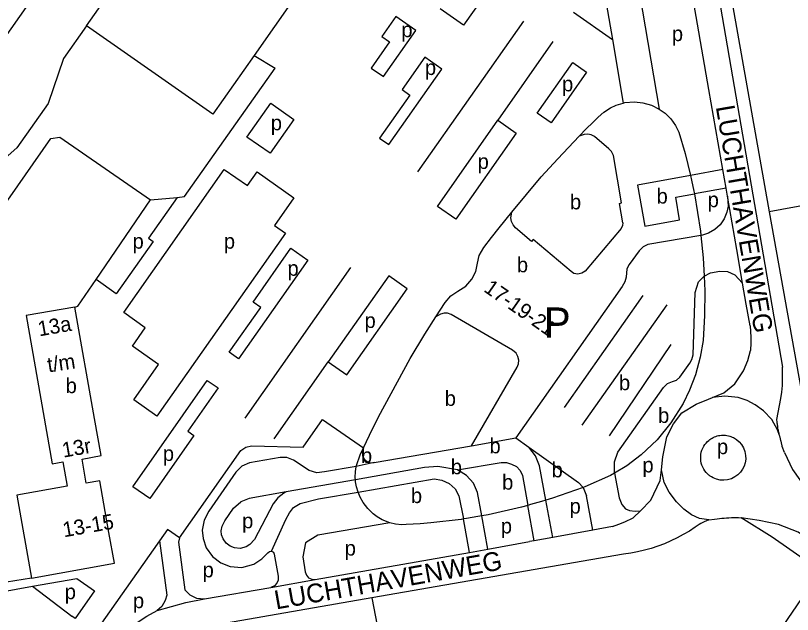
# Model space of a CAD drawing. Extents: x 154765 to 156627, y 383996 to 386132.
# Drawn here: x 155215.9 to 155422.2, y 385255.7 to 385414.8 of the extents above; entities that cross this region are included whole.
import ezdxf

# ---------------------------------------------------------------- set-up
doc = ezdxf.new("R2010")
doc.units = 0
for name, color, linetype in [('BLT_Basislijn', 7, 'Continuous'), ('BLT_Bebouwing', 7, 'Continuous'), ('BLT_Centroide', 7, 'Continuous'), ('BLT_Huisnummer_reeks', 7, 'Continuous'), ('BLT_Huisnummer_zonder_bebouwing', 7, 'Continuous'), ('BLT_Onderdoorgang_en_onderverdeling', 7, 'Continuous'), ('BLT_Straatnaam', 7, 'Continuous'), ('BLT_Tekst_parkeren', 7, 'Continuous'), ('BLT_Vlakafsluiter', 7, 'Continuous')]:
    doc.layers.add(name, color=color, linetype=linetype)

msp = doc.modelspace()

# ---------------------------------------------------------------- linework, layer by layer
at = {"layer": 'BLT_Basislijn'}
for p, q in [((155400.95, 385429.81), (155412.57, 385362.07)), ((155371.37, 385426.14), (155374.46, 385408.44)), ((155396.62, 385414.57), (155394.55, 385426.48)), ((155364.08, 385415.71), (155374.46, 385408.44)), ((155400, 385395.22), (155396.62, 385414.57)), ((155322.73, 385373.28), (155350.85, 385413.37)), ((155374.46, 385408.44), (155377.24, 385391.55)), ((155358.59, 385407.92), (155343.96, 385387.02)), ((155279.2, 385404.25), (155284.8, 385400.85)), ((155403.72, 385373.9), (155400, 385395.22)), ((155327.92, 385364.12), (155343.96, 385387.02)), ((155403.72, 385373.9), (155395.16, 385372.34)), ((155404.58, 385368.97), (155403.72, 385373.9)), ((155474.85, 385373.32), (155416.02, 385362.7)), ((155404.58, 385368.97), (155396.18, 385367.45)), ((155404.95, 385366.84), (155404.58, 385368.97)), ((155237.25, 385344.69), (155251.67, 385365.82)), ((155251.67, 385365.82), (155258.78, 385366.52)), ((155405.58, 385363.26), (155404.95, 385366.84)), ((155412.57, 385362.07), (155419.55, 385321.41)), ((155382.97, 385358.91), (155392.22, 385360.52)), ((155276.82, 385307.81), (155304.95, 385347.9)), ((155314.97, 385345.7), (155298.92, 385322.81)), ((155409.96, 385338.15), (155408.99, 385343.7)), ((155361.7, 385310.69), (155382.58, 385340.45)), ((155410.96, 385332.4), (155409.96, 385338.15)), ((155366.4, 385305.99), (155388.93, 385338)), ((155373.65, 385303.17), (155390.01, 385327.45)), ((155284.59, 385302.37), (155298.92, 385322.81)), ((155336.98, 385300.52), (155348.75, 385302.59)), ((155348.75, 385302.59), (155352.16, 385300.17)), ((155311.09, 385296.05), (155306.36, 385295.03)), ((155306.16, 385291.46), (155287.78, 385288.26)), ((155366.63, 385289.43), (155367.52, 385287.19)), ((155369.19, 385278.13), (155367.52, 385287.19)), ((155353.63, 385275.27), (155351.9, 385284.69)), ((155358.55, 385276.17), (155356.74, 385286.07)), ((155336.41, 385272.2), (155334.83, 385281.08)), ((155341.34, 385273.08), (155339.76, 385281.92)), ((155416.84, 385276.27), (155408.56, 385281.41)), ((155369.19, 385278.13), (155358.55, 385276.17)), ((155429.71, 385267.2), (155416.84, 385276.27)), ((155341.34, 385273.08), (155352.42, 385275.05)), ((155353.63, 385275.27), (155352.42, 385275.05)), ((155295.4, 385264.98), (155336.41, 385272.2)), ((155377.39, 385271.68), (155310.52, 385260.07)), ((155220.38, 385263.19), (155230.84, 385255.22)), ((155266.03, 385259.85), (155283.71, 385262.9)), ((155310.52, 385260.07), (155271.92, 385253.37))]:
    msp.add_line(p, q, dxfattribs=at)
for points in [[(155001.53, 385107.93), (155095.72, 385242.01), (155221.63, 385421.26), (155278.06, 385501.59), (155307.92, 385531.59), (155362.73, 385609.97), (155374.64, 385636.58)], [(155392.42, 385436.89), (155391.77, 385437.82), (155390.87, 385438.4), (155389.63, 385438.52), (155381.11, 385437.02), (155380.12, 385436.47), (155379.44, 385435.48), (155379.34, 385433.81), (155386.86, 385389.98)], [(155402.92, 385436.68), (155416.02, 385362.7)], [(155234.74, 385412.07), (155228.58, 385403.41), (155224.55, 385391.47), (155216.21, 385379.72), (155192.97, 385359.25), (155123.67, 385259.51), (155043.61, 385145.9), (155014.37, 385104.41), (155012.61, 385102.8), (155010.41, 385101.87), (155008.28, 385101.81), (155005.41, 385102.5), (155003.02, 385104.02), (155002.04, 385105.22), (155001.66, 385106.08), (155001.51, 385106.85), (155001.53, 385107.93)], [(155258.78, 385366.52), (155260.76, 385366.72), (155284.8, 385400.85)], [(155343.96, 385387.02), (155348.85, 385383.6), (155332.82, 385360.69), (155327.92, 385364.12)], [(155204.86, 385334.76), (155196.2, 385340.65), (155225.22, 385382.15), (155227.66, 385382.48), (155251.67, 385365.82)], [(155244.59, 385335.89), (155271.3, 385373.92), (155277.45, 385369.63), (155280.03, 385373.3), (155289.81, 385366.41), (155284.68, 385359.05), (155287.55, 385357.05), (155253.4, 385308.38), (155247.26, 385312.69), (155253.84, 385322.09), (155246.89, 385326.95), (155250.33, 385331.87), (155244.59, 385335.89)], [(155395.16, 385372.34), (155381.1, 385369.79), (155382.97, 385358.91)], [(155392.22, 385360.52), (155391.26, 385366.55), (155396.18, 385367.45)], [(155258.78, 385366.52), (155251.19, 385355.68), (155252.4, 385354.83), (155242.62, 385340.88), (155237.25, 385344.69)], [(155404.95, 385366.84), (155405.13, 385364.18), (155404.83, 385362.62), (155404.12, 385360.83), (155403.02, 385359.23), (155401.58, 385357.94), (155399.91, 385356.97), (155398.31, 385356.5), (155397.89, 385356.43)], [(155416.02, 385362.7), (155424.54, 385315.33), (155428.63, 385292.55)], [(155397.89, 385356.43), (155383.82, 385353.98), (155382.55, 385353.4), (155381.48, 385352.35), (155378.83, 385348.67), (155378.25, 385347.51), (155378.05, 385345.32), (155377.66, 385344.1), (155376.98, 385342.86), (155348.75, 385302.59)], [(155398.77, 385345.57), (155400.48, 385346.48), (155402.91, 385346.91), (155405, 385346.8), (155406.9, 385345.93), (155408.99, 385343.7)], [(155231.6, 385337.38), (155232.43, 385337.63), (155237.25, 385344.69)], [(155298.92, 385322.81), (155303.84, 385319.38), (155319.88, 385342.25), (155314.97, 385345.7)], [(155374.99, 385293.2), (155374.99, 385296.29), (155375.88, 385298.84), (155387.96, 385315.97), (155389.07, 385317.04), (155390.32, 385317.58), (155391.4, 385317.96), (155392.31, 385318.71), (155394.95, 385322.46), (155395.48, 385323.45), (155395.81, 385324.68), (155396.36, 385341.26), (155397.29, 385344.05), (155398.77, 385345.57)], [(155410.96, 385332.4), (155411.12, 385330.88), (155411.19, 385329.36), (155411.19, 385327.83), (155411.08, 385325.79)], [(155401, 385313.38), (155403.98, 385314.62), (155406.89, 385316.94), (155409.23, 385320.46), (155410.36, 385323.19), (155411.08, 385325.79)], [(155418.1, 385307.52), (155419.14, 385313.09), (155419.38, 385314.79), (155419.54, 385316.51), (155419.61, 385318.23), (155419.61, 385319.95), (155419.55, 385321.41)], [(155387.42, 385294.14), (155387.77, 385297.57), (155388.84, 385302.88), (155390.62, 385306.34), (155392.85, 385309.26), (155396.61, 385311.57), (155399.89, 385312.93), (155401, 385313.38)], [(155259.45, 385276.02), (155275.72, 385299.27), (155276.99, 385300.17), (155278.51, 385300.48), (155292.22, 385300.17), (155297.37, 385307.52), (155308.27, 385299.95)], [(155418.81, 385303.25), (155418.74, 385303.52), (155418.67, 385303.79), (155418.6, 385304.06), (155418.54, 385304.33), (155418.49, 385304.6), (155418.43, 385304.88), (155418.38, 385305.15), (155418.34, 385305.43), (155418.3, 385305.7), (155418.26, 385305.98), (155418.22, 385306.26), (155418.19, 385306.54), (155418.16, 385306.81), (155418.1, 385307.52)], [(155400, 385301.95), (155400.27, 385302.17), (155400.57, 385302.37), (155400.87, 385302.56), (155401.2, 385302.73), (155401.53, 385302.88), (155401.88, 385303.01), (155402.24, 385303.12), (155402.6, 385303.21), (155402.97, 385303.28), (155403.35, 385303.32), (155403.72, 385303.34), (155404.1, 385303.34), (155404.47, 385303.31), (155404.84, 385303.26), (155405.2, 385303.18), (155405.55, 385303.09), (155405.89, 385302.98), (155406.22, 385302.84), (155406.54, 385302.7)], [(155420.11, 385298.76), (155419.52, 385300.32), (155419.49, 385300.47), (155419.46, 385300.63), (155419.42, 385300.78), (155419.39, 385300.94), (155419.35, 385301.09), (155419.32, 385301.25), (155419.28, 385301.4), (155419.24, 385301.55), (155419.21, 385301.71), (155419.17, 385301.86), (155419.13, 385302.02), (155419.09, 385302.17), (155419.05, 385302.33), (155419.01, 385302.48), (155418.97, 385302.63), (155418.93, 385302.79), (155418.89, 385302.94), (155418.85, 385303.09), (155418.81, 385303.25)], [(155400, 385292.75), (155399.63, 385293.08), (155399.29, 385293.45), (155398.96, 385293.87), (155398.66, 385294.32), (155398.41, 385294.82), (155398.19, 385295.34), (155398.02, 385295.9), (155397.91, 385296.47), (155397.85, 385297.06), (155397.85, 385297.65), (155397.91, 385298.23), (155398.02, 385298.81), (155398.19, 385299.36), (155398.41, 385299.89), (155398.66, 385300.38), (155398.96, 385300.83), (155399.29, 385301.25), (155399.63, 385301.62), (155400, 385301.95)], [(155406.54, 385302.7), (155407.32, 385302.22), (155408.05, 385301.6), (155408.7, 385300.84), (155409.22, 385299.96), (155409.59, 385298.99), (155409.79, 385297.97), (155409.8, 385296.96), (155409.66, 385295.99), (155409.38, 385295.1), (155408.97, 385294.29), (155408.43, 385293.52), (155407.74, 385292.82), (155406.92, 385292.23), (155406, 385291.77), (155405, 385291.48), (155403.99, 385291.37), (155402.99, 385291.42), (155402.05, 385291.63), (155401.2, 385291.97)], [(155356.74, 385286.07), (155355.05, 385295.15), (155353.93, 385297.88), (155352.16, 385300.17)], [(155352.16, 385300.17), (155365.37, 385290.8), (155366.63, 385289.43)], [(155306.36, 385295.03), (155297.93, 385293.57), (155295.9, 385293.37), (155293.87, 385293.92), (155289.67, 385296.67), (155287.96, 385297.36), (155286.11, 385297.39), (155277.99, 385295.96), (155275.94, 385295.06), (155274.37, 385293.46), (155267.17, 385283.18), (155265.94, 385280.78), (155265.47, 385278.13), (155265.65, 385275.86), (155266.49, 385273.43), (155268.15, 385271.1), (155270.35, 385269.42), (155272.86, 385268.44), (155275.96, 385268.2), (155279.15, 385269.05), (155281.31, 385270.44), (155282.84, 385272.09), (155283.32, 385272.46), (155283.88, 385272.48)], [(155420.11, 385298.76), (155422.23, 385294.2), (155425.65, 385289.38), (155428.46, 385286.31), (155495.6, 385239.29)], [(155333.27, 385294.1), (155328.03, 385295.03), (155324.48, 385294.7), (155306.16, 385291.46)], [(155333.27, 385294.1), (155344.83, 385296.07), (155346.27, 385296.07), (155347.64, 385295.65), (155348.91, 385294.97), (155349.93, 385293.95), (155350.51, 385292.63), (155351.9, 385284.69)], [(155339.76, 385281.92), (155338.6, 385288.08), (155337.46, 385290.59), (155335.63, 385292.66), (155333.27, 385294.1)], [(155374.99, 385293.2), (155376.19, 385286.65), (155376.9, 385284.87), (155377.9, 385283.79), (155378.94, 385283.33), (155380.41, 385283.12), (155381.82, 385283.25)], [(155381.82, 385283.25), (155384.63, 385286.07), (155387.13, 385291.29), (155387.42, 385294.14)], [(155401.2, 385291.97), (155400.74, 385292.22), (155400.36, 385292.47), (155400.3, 385292.52), (155400.18, 385292.61), (155400, 385292.75)], [(155306.84, 385288.21), (155327.04, 385291.7), (155329.13, 385291.42), (155331.05, 385290.52), (155332.59, 385289.07), (155333.64, 385287.24), (155334.83, 385281.08)], [(155287.78, 385288.26), (155287.08, 385287.95), (155285.51, 385286.67), (155284.31, 385285.13), (155279.31, 385275.63), (155278.07, 385274.3), (155277.11, 385273.68), (155275.5, 385273.25), (155273.99, 385273.37), (155272.83, 385273.82), (155271.79, 385274.62), (155270.98, 385275.75), (155270.58, 385276.89), (155270.51, 385277.89), (155270.73, 385279.17), (155271.46, 385280.59), (155273.78, 385283.91), (155275.71, 385285.63)], [(155287.78, 385288.26), (155277.88, 385286.54), (155275.71, 385285.63)], [(155283.88, 385272.48), (155287.65, 385280.93), (155288.66, 385282.67), (155289.69, 385284.08), (155291.5, 385285.18), (155296.33, 385286.4), (155306.84, 385288.21)], [(155400, 385280.8), (155398.78, 385280.33), (155397.88, 385279.84), (155397.45, 385279.6), (155396.4, 385278.86)], [(155400, 385280.8), (155401.56, 385281.04), (155402.19, 385281.13), (155402.82, 385281.2), (155403.46, 385281.27), (155404.09, 385281.32), (155404.73, 385281.37), (155405.37, 385281.4), (155406.01, 385281.42), (155406.65, 385281.44), (155407.28, 385281.44), (155407.92, 385281.43), (155408.56, 385281.41)], [(155432.59, 385271.29), (155423.74, 385277.53), (155418.53, 385279.58), (155413.38, 385280.64), (155408.56, 385281.41)], [(155259.45, 385276.02), (155256.19, 385278.3), (155254.07, 385275.28)], [(155315.32, 385280.04), (155296.16, 385276.77), (155292.92, 385274.73), (155292.13, 385270.98), (155292.79, 385266.99), (155293.11, 385266.13), (155293.7, 385265.47), (155294.53, 385265.06), (155295.4, 385264.98)], [(155396.4, 385278.86), (155394.84, 385277.85), (155393.24, 385276.9), (155391.6, 385276.02), (155389.92, 385275.22), (155388.21, 385274.49), (155386.46, 385273.83), (155384.7, 385273.24), (155382.9, 385272.74), (155381.09, 385272.31), (155379.27, 385271.96), (155377.39, 385271.68)], [(155254.07, 385275.28), (155238.1, 385252.48), (155236.88, 385253.34), (155229.4, 385242.68)], [(155254.07, 385275.28), (155256.01, 385260.8), (155255.64, 385259.42), (155254.7, 385257.83), (155253.51, 385256.71)], [(155259.45, 385276.02), (155259.16, 385274.94), (155260.86, 385262.27), (155262.17, 385260.89), (155263.96, 385260.03), (155266.03, 385259.85)], [(155283.88, 385272.48), (155284.34, 385272.21), (155284.59, 385271.69), (155285.61, 385265.87), (155285.63, 385264.83), (155285.29, 385263.98), (155284.66, 385263.31), (155283.71, 385262.9)], [(155393.24, 385209.32), (155391.13, 385210.77), (155429.71, 385267.2)], [(155220.06, 385265.38), (155211.16, 385263.89), (155211.57, 385261.6), (155220.38, 385263.19)], [(155220.38, 385263.19), (155232.1, 385265.26), (155236.79, 385261.97), (155231.66, 385254.64), (155230.84, 385255.22)], [(155253.51, 385256.71), (155261.05, 385258.86), (155266.03, 385259.85)], [(155310.52, 385260.07), (155314.18, 385240.81)], [(155248.17, 385253.56), (155250.76, 385255.2), (155253.51, 385256.71)]]:
    msp.add_lwpolyline(points, dxfattribs=at)
for points in [[(155316.89, 385414.57), (155313.19, 385409.29), (155315.23, 385407.86), (155310.35, 385400.89), (155313.62, 385398.59), (155322.21, 385410.86)], [(155312.54, 385382.26), (155315, 385380.53), (155329.06, 385400.6), (155324.54, 385403.74), (155318.54, 385395.16), (155320.58, 385393.71)], [(155363.87, 385402.39), (155367.56, 385399.78), (155358.09, 385386.29), (155354.44, 385388.88)], [(155283.64, 385391.52), (155289.78, 385387.22), (155283.47, 385378.22), (155277.31, 385382.53)], [(155288.98, 385352.99), (155293.46, 385349.82), (155275.1, 385323.65), (155272.64, 385325.37), (155280.99, 385337.27), (155278.94, 385338.68)], [(155266.79, 385317.89), (155269.65, 385315.88), (155261.61, 385304.39), (155263.24, 385303.26), (155251.51, 385286.48), (155247.03, 385289.62)]]:
    msp.add_lwpolyline(points, close=True, dxfattribs=at)
at = {"layer": 'BLT_Bebouwing'}
for p, q in [((155234.74, 385412.07), (155261.63, 385451)), ((155301.33, 385435.8), (155279.2, 385404.25)), ((155268.23, 385388.61), (155234.74, 385412.07)), ((155279.2, 385404.25), (155268.23, 385388.61)), ((155375.38, 385391.03), (155377.24, 385391.55)), ((155220.06, 385265.38), (155242.15, 385269.29))]:
    msp.add_line(p, q, dxfattribs=at)
for points in [[(155348.18, 385419.98), (155342.9, 385423.71), (155334.85, 385412.23), (155328.66, 385416.58)], [(155377.24, 385391.55), (155377.74, 385391.69), (155380.29, 385391.9), (155382.48, 385391.68), (155384.81, 385391), (155386.86, 385389.98)], [(155365.58, 385382.75), (155367.52, 385384.79), (155369.09, 385386.34), (155370.64, 385387.85), (155372.13, 385389.14), (155373.85, 385390.31), (155375.38, 385391.03)], [(155386.86, 385389.98), (155388.38, 385388.88), (155389.91, 385387.38), (155391.18, 385385.61), (155392.07, 385383.84), (155393.72, 385378.14), (155395.16, 385372.34)], [(155347.72, 385362.57), (155355.51, 385371.95), (155359.88, 385376.78), (155365.58, 385382.75)], [(155395.16, 385372.34), (155395.43, 385371.11), (155396.04, 385368.18), (155396.18, 385367.45)], [(155396.18, 385367.45), (155397.76, 385357.51), (155397.89, 385356.43)], [(155327.54, 385334.8), (155329.95, 385338.57), (155331.49, 385340.4), (155333.36, 385341.57), (155335.44, 385342.9), (155337.09, 385344.75), (155338.13, 385346.83), (155338.59, 385349.02), (155339.05, 385351.06), (155340.26, 385353.21), (155342.26, 385355.84), (155344.28, 385358.44), (155347.72, 385362.57)], [(155397.89, 385356.43), (155398.48, 385350.42), (155398.77, 385345.57)], [(155398.77, 385345.57), (155398.92, 385341.66), (155398.89, 385335.14), (155398.52, 385328.45), (155397.75, 385324.02), (155396.47, 385319.4), (155394.88, 385315.26), (155393.16, 385311.72), (155389.93, 385306.57), (155386.29, 385302.13), (155382.04, 385298.1), (155378.19, 385295.19), (155374.99, 385293.2)], [(155231.6, 385337.38), (155218.64, 385335.1), (155225.56, 385295.74), (155228.43, 385296.24)], [(155236.82, 385307.8), (155231.6, 385337.38)], [(155308.27, 385299.95), (155309.88, 385303.32), (155312.3, 385308.23), (155320.69, 385323.67), (155324.58, 385330.17), (155327.54, 385334.8)], [(155233.52, 385297), (155238.56, 385297.89), (155236.82, 385307.8)], [(155306.36, 385295.03), (155307.52, 385298.38), (155308.27, 385299.95)], [(155242.15, 385269.29), (155240.6, 385277.48), (155239.63, 385283.08), (155238.26, 385291.18), (155234.62, 385290.56), (155233.52, 385297)], [(155228.43, 385296.24), (155229.58, 385289.76), (155216.16, 385287.38), (155220.06, 385265.38)], [(155306.16, 385291.46), (155306.11, 385292.12), (155306.16, 385293.69), (155306.34, 385294.96), (155306.36, 385295.03)], [(155374.99, 385293.2), (155373.92, 385292.61), (155367.09, 385289.59), (155366.63, 385289.43)], [(155306.84, 385288.21), (155306.43, 385289.59), (155306.2, 385290.97), (155306.16, 385291.46)], [(155366.63, 385289.43), (155358.48, 385286.58), (155356.74, 385286.07)], [(155315.32, 385280.04), (155313.23, 385280.88), (155311.93, 385281.63), (155310.84, 385282.44), (155309.4, 385283.85), (155308.19, 385285.46), (155307.4, 385286.85), (155306.84, 385288.21)], [(155351.9, 385284.69), (155350.21, 385284.21), (155341.42, 385282.2), (155339.76, 385281.92)], [(155356.74, 385286.07), (155355.53, 385285.71), (155352.65, 385284.9), (155351.9, 385284.69)], [(155334.83, 385281.08), (155334.2, 385280.97), (155326.16, 385280.02), (155323.34, 385279.79), (155319.61, 385279.56), (155318.46, 385279.52), (155316.79, 385279.7), (155315.32, 385280.04)], [(155339.76, 385281.92), (155338.61, 385281.72), (155335.66, 385281.22), (155334.83, 385281.08)]]:
    msp.add_lwpolyline(points, dxfattribs=at)
at = {"layer": 'BLT_Onderdoorgang_en_onderverdeling'}
msp.add_line((155311.09, 385296.05), (155336.98, 385300.52), dxfattribs=at)
for points in [[(155377.17, 385359.72), (155376.27, 385364.93), (155376.84, 385365.03), (155374.67, 385377.64), (155374.19, 385378.73), (155373.48, 385379.45), (155369.64, 385382.66), (155368.79, 385383.12), (155367.84, 385383.32), (155366.88, 385383.25), (155365.58, 385382.75)], [(155377.17, 385359.72), (155377.12, 385359), (155376.74, 385358.21), (155367.18, 385346.95), (155366.28, 385346.35), (155365.22, 385346.12), (155364.16, 385346.33), (155363.42, 385346.79), (155353.33, 385355.29), (155352.94, 385354.83), (155348.69, 385358.45), (155348.01, 385359.2), (155347.59, 385360.12), (155347.46, 385361.12), (155347.72, 385362.57)], [(155336.98, 385300.52), (155349.06, 385321.36), (155349.46, 385322.28), (155349.53, 385323.28), (155349.32, 385324.26), (155348.81, 385325.12), (155347.88, 385325.91), (155331.56, 385335.42), (155330.64, 385335.73), (155329.67, 385335.77), (155328.74, 385335.52), (155327.54, 385334.8)], [(155308.27, 385299.95), (155307.96, 385298.91), (155308.03, 385297.9), (155308.46, 385296.99), (155309.22, 385296.33), (155310.16, 385296), (155311.09, 385296.05)]]:
    msp.add_lwpolyline(points, dxfattribs=at)
at = {"layer": 'BLT_Vlakafsluiter'}
for p, q in [((155407.43, 385352.66), (155405.58, 385363.26)), ((155408.99, 385343.7), (155407.43, 385352.66)), ((155374.45, 385279.09), (155369.19, 385278.13)), ((155358.55, 385276.17), (155353.63, 385275.27)), ((155336.41, 385272.2), (155341.34, 385273.08)), ((155283.71, 385262.9), (155295.4, 385264.98))]:
    msp.add_line(p, q, dxfattribs=at)
for points in [[(155418.81, 385303.25), (155418.24, 385304.71), (155416.71, 385307.46), (155414.53, 385309.77), (155412.3, 385311.42), (155410.23, 385312.56), (155407.84, 385313.32), (155404.23, 385313.68), (155401, 385313.38)], [(155400, 385280.8), (155397.52, 385281.19), (155395.41, 385282.21), (155393.37, 385283.64), (155391.39, 385285.6), (155389.45, 385288.21), (155388.16, 385290.79), (155387.42, 385294.14)], [(155379.94, 385281.38), (155381.82, 385283.25)], [(155374.45, 385279.09), (155376.08, 385279.67), (155377.67, 385280.33), (155379.94, 385281.38)]]:
    msp.add_lwpolyline(points, dxfattribs=at)

# ---------------------------------------------------------------- texts
at = {"layer": 'BLT_Centroide'}
for s, p in [('p', (155318.34, 385409.09)), ('p', (155390.2, 385408.03)), ('p', (155324.6, 385399.03)), ('p', (155361.02, 385394.69)), ('p', (155283.66, 385384.34)), ('p', (155338.6, 385374.07)), ('b', (155386.14, 385364.87)), ('b', (155363.13, 385363.33)), ('p', (155399.71, 385363.91)), ('p', (155246.94, 385352.88)), ('p', (155271.19, 385352.88)), ('b', (155349.03, 385346.61)), ('p', (155288.09, 385345.68)), ('p', (155308.56, 385331.82)), ('b', (155376.15, 385315.29)), ('b', (155229.17, 385314.5)), ('b', (155329.86, 385311.11)), ('b', (155386.53, 385306.59)), ('b', (155341.75, 385298.51)), ('p', (155402.18, 385298.28)), ('p', (155254.98, 385296.48)), ('b', (155307.61, 385295.95)), ('b', (155331.47, 385292.95)), ('b', (155358.25, 385292.13)), ('p', (155382.37, 385293.42)), ('b', (155345.1, 385288.86)), ('b', (155320.88, 385285.29)), ('p', (155363.02, 385282.49)), ('p', (155276.04, 385278.59)), ('p', (155344.76, 385277.22)), ('p', (155303.29, 385271.33)), ('p', (155265.55, 385265.56)), ('p', (155228.92, 385259.75)), ('p', (155247.04, 385257.37))]:
    msp.add_text(s, height=4, dxfattribs=at).set_placement(p)
at = {"layer": 'BLT_Huisnummer_reeks'}
for s, rotation, p in [('13a', 9.9307, (155222.15, 385329.57)), ('t/m', 8.511, (155224.6, 385320.01)), ('13r', 9.9307, (155228.56, 385297.35)), ('13-15', 9.9307, (155228.73, 385276.19))]:
    msp.add_text(s, height=4, rotation=rotation, dxfattribs=at).set_placement(p)
at = {"layer": 'BLT_Huisnummer_zonder_bebouwing'}
msp.add_text('17-19-21', height=4, rotation=325, dxfattribs=at).set_placement((155339.97, 385341.69))
at = {"layer": 'BLT_Straatnaam'}
for rotation, p in [(279.7374, (155401.84, 385390.6)), (10.0452, (155285.07, 385257.01))]:
    msp.add_text('LUCHTHAVENWEG', height=5, rotation=rotation, dxfattribs=at).set_placement(p)
at = {"layer": 'BLT_Tekst_parkeren'}
msp.add_text('P', height=8, rotation=359.9654, dxfattribs=at).set_placement((155356.17, 385329.26))

doc.saveas('drawing.dxf')
